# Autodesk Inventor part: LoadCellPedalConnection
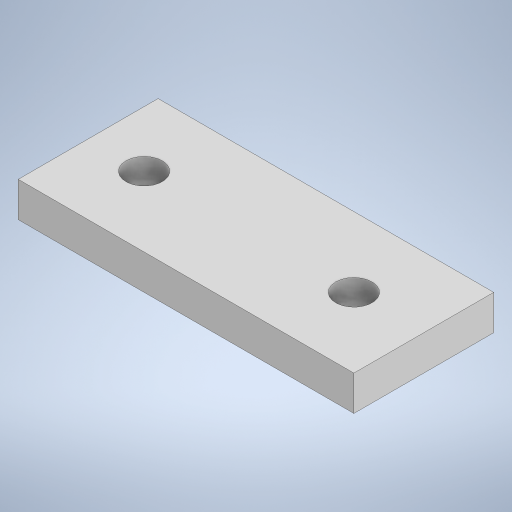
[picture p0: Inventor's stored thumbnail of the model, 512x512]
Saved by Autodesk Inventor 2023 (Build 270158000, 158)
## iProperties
Created: 2023-06
Part Number: LoadCellPedalConnection
Material: Generic
Document SubType Name: Modeling
Designer: Admin
Density: 1 g/cm^3
Appearance: Default
Author: Admin
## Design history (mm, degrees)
sketch "Sketch1"
  geometry: L1 (0, 0)-(48, 0); L2 (48, 0)-(48, -20); L3 (48, -20)-(0, -20); L4 (0, -20)-(0, 0); L5 (40, -10)-(10, -10); L6 (10, -10)-(0, -10); C1 r 2.6 at (40, -10); C2 r 2.6 at (10, -10)
  constraints: 12 end point, 3 parallel, 2 centre point, 1 equal radius, 1 horizontal, 1 midpoint, 1 perpendicular
  dimensions: "d0" = 20 distance between parallel lines of L3 L1; "d2" = 30 distance of L5.start L5.end; "d3" = 8 distance from line of L5.start L2; "d4" = 10 distance from line of L4 L5.end; "d5" = 5.2 diameter of C1
extrude "Extrusion1" new body sketch "Sketch1" distance "d6" = 5; taper "d7" = 0 deg
body "Solid1"
